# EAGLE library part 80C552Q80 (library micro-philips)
MICROCONTROLLER
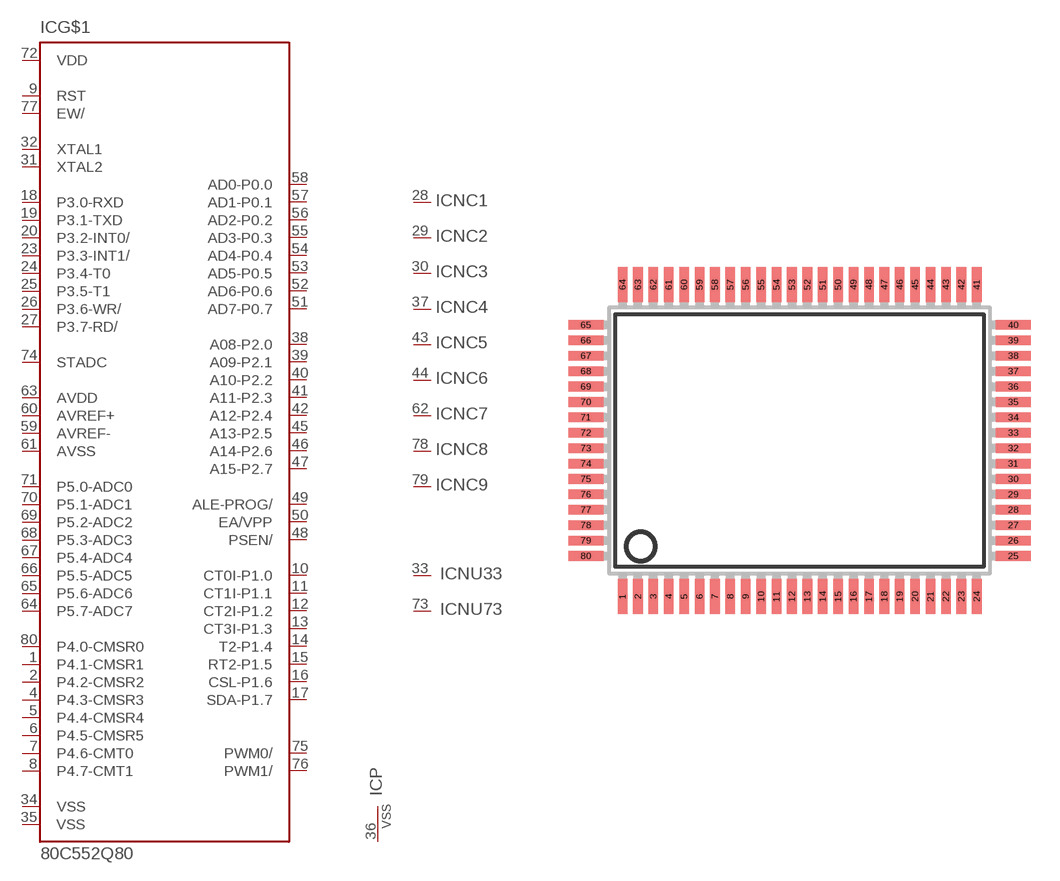
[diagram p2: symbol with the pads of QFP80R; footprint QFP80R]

Designator prefix IC; gates G$1=80C552 NC1=NC NC2=NC NC3=NC NC4=NC NC5=NC NC6=NC NC7=NC NC8=NC NC9=NC P=VSS NU33=NU NU73=NU

## 80C552Q80 (OC_FARNELL: unknown; OC_NEWARK: unknown)  [QFP80R]
1  G$1:P4.1-CMSR1
2  G$1:P4.2-CMSR2
3  G$1:NC1  nc
4  G$1:P4.3-CMSR3
5  G$1:P4.4-CMSR4
6  G$1:P4.5-CMSR5
7  G$1:P4.6-CMT0
8  G$1:P4.7-CMT1
9  G$1:RST
10  G$1:CT0I-P1.0
11  G$1:CT1I-P1.1
12  G$1:CT2I-P1.2
13  G$1:CT3I-P1.3
14  G$1:T2-P1.4
15  G$1:RT2-P1.5
16  G$1:CSL-P1.6
17  G$1:SDA-P1.7
18  G$1:P3.0-RXD
19  G$1:P3.1-TXD
20  G$1:P3.2-INT0/
21  G$1:NC2  nc
22  G$1:NC3  nc
23  G$1:P3.3-INT1/
24  G$1:P3.4-T0
25  G$1:P3.5-T1
26  G$1:P3.6-WR/
27  G$1:P3.7-RD/
28  NC1:NC  nc
29  NC2:NC  nc
30  NC3:NC  nc
31  G$1:XTAL2  out
32  G$1:XTAL1  in
33  NU33:IC-NU  nc
34  G$1:VSS  pwr
35  G$1:VSS  pwr
36  P:VSS  pwr
37  NC4:NC  nc
38  G$1:A08-P2.0
39  G$1:A09-P2.1
40  G$1:A10-P2.2
41  G$1:A11-P2.3
42  G$1:A12-P2.4
43  NC5:NC  nc
44  NC6:NC  nc
45  G$1:A13-P2.5
46  G$1:A14-P2.6
47  G$1:A15-P2.7
48  G$1:PSEN/  out
49  G$1:ALE-PROG/  out
50  G$1:EA/VPP  in
51  G$1:AD7-P0.7
52  G$1:AD6-P0.6
53  G$1:AD5-P0.5
54  G$1:AD4-P0.4
55  G$1:AD3-P0.3
56  G$1:AD2-P0.2
57  G$1:AD1-P0.1
58  G$1:AD0-P0.0
59  G$1:AVREF-  in
60  G$1:AVREF+  in
61  G$1:AVSS  in
62  NC7:NC  nc
63  G$1:AVDD  in
64  G$1:P5.7-ADC7
65  G$1:P5.6-ADC6
66  G$1:P5.5-ADC5
67  G$1:P5.4-ADC4
68  G$1:P5.3-ADC3
69  G$1:P5.2-ADC2
70  G$1:P5.1-ADC1
71  G$1:P5.0-ADC0
72  G$1:VDD  pwr
73  NU73:IC-NU  nc
74  G$1:STADC  in
75  G$1:PWM0/  out
76  G$1:PWM1/  out
77  G$1:EW/  in
78  NC8:NC  nc
79  NC9:NC  nc
80  G$1:P4.0-CMSR0

## Footprint QFP80R (pad centres in mm)
Quad Flat Pack Package 80 Pin Rectangle
smd 0.5 x 1.8: 1 -9.2,-8.1; 2 -8.4,-8.1; 3 -7.6,-8.1; 4 -6.8,-8.1; 5 -6,-8.1; 6 -5.2,-8.1; 7 -4.4,-8.1; 8 -3.6,-8.1; 9 -2.8,-8.1; 10 -2,-8.1; 11 -1.2,-8.1; 12 -0.4,-8.1; 13 0.4,-8.1; 14 1.2,-8.1; 15 2,-8.1; 16 2.8,-8.1; 17 3.6,-8.1; 18 4.4,-8.1; 19 5.2,-8.1; 20 6,-8.1; 21 6.8,-8.1; 22 7.6,-8.1; 23 8.4,-8.1; 24 9.2,-8.1; 41 9.2,8.1; 42 8.4,8.1; 43 7.6,8.1; 44 6.8,8.1; 45 6,8.1; 46 5.2,8.1; 47 4.4,8.1; 48 3.6,8.1; 49 2.8,8.1; 50 2,8.1; 51 1.2,8.1; 52 0.4,8.1; 53 -0.4,8.1; 54 -1.2,8.1; 55 -2,8.1; 56 -2.8,8.1; 57 -3.6,8.1; 58 -4.4,8.1; 59 -5.2,8.1; 60 -6,8.1; 61 -6.8,8.1; 62 -7.6,8.1; 63 -8.4,8.1; 64 -9.2,8.1
smd 1.8 x 0.5: 25 11.1,-6; 26 11.1,-5.2; 27 11.1,-4.4; 28 11.1,-3.6; 29 11.1,-2.8; 30 11.1,-2; 31 11.1,-1.2; 32 11.1,-0.4; 33 11.1,0.4; 34 11.1,1.2; 35 11.1,2; 36 11.1,2.8; 37 11.1,3.6; 38 11.1,4.4; 39 11.1,5.2; 40 11.1,6; 65 -11.1,6; 66 -11.1,5.2; 67 -11.1,4.4; 68 -11.1,3.6; 69 -11.1,2.8; 70 -11.1,2; 71 -11.1,1.2; 72 -11.1,0.4; 73 -11.1,-0.4; 74 -11.1,-1.2; 75 -11.1,-2; 76 -11.1,-2.8; 77 -11.1,-3.6; 78 -11.1,-4.4; 79 -11.1,-5.2; 80 -11.1,-6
